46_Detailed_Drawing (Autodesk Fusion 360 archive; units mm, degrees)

design "46 Detailed Drawing"
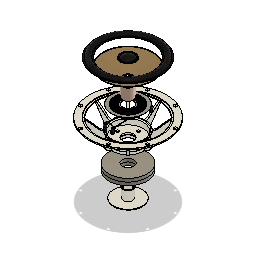
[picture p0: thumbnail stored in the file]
part number: 6 Inch Woofer
parameter "VoiceCoilDia" = 30
parameter "VoiceCoilThickness" = 2
parameter "PoleDia" = 22 (= "VoiceCoilDia + -4 * VoiceCoilThickness")
parameter "BasketThickness" = 3
parameter "SpiderMountingSurface" = 46 (= "SpacerDiameter / 2 + 2 * BasketThickness")
parameter "adsk_nomlen" = 10
parameter "adsk_headh" = 2.7
parameter "adsk_headdia" = 9.3
parameter "adsk_nomdia" = 5
parameter "adsk_headang" = 90
parameter "adsk_phildia" = 5.2
parameter "adsk_philwidth" = 0.66
parameter "adsk_phildepth" = 3.2
parameter "adsk_shnkdia" = 4.5092
parameter "adsk_thrlen" = 5.7
parameter "adsk_pitch1" = 0.8
parameter "adsk_startlen" = 0.4908
parameter "adsk_midfillet" = 0.5 (= "adsk_nomdia * 0.1")
parameter "adsk_endpointdia" = 4.0185
parameter "MountingHoleDia" = 86.2 (= "( ( SpeakerSize * 25.4 / 2 ) * 1 mm ) + ( FlangeSize / 2 )")
parameter "ConeAngle" = 70
parameter "CoverThickness" = 2.5
sketch "Sketch1" plane through (0, 0, 0) normal (0, 1, 0) x axis (1, 0, 0)
  circle C1 centre (0, 0) radius 50
  circle C2 centre (0, 0) radius 18
  point P1 (0, 0)
  point P2 (0, 0)
  point P3 (0, 0)
  coincident P1 P2
  coincident P1 P3
  dimension "MagnetDia" diameter C1 = 100
  dimension "MagnetThruHole" diameter C2 = 36 (= "VoiceCoilDia + 3 * VoiceCoilThickness")
extrude "Extrude1" new body sketch "Sketch1" along normal blind 10 named "MagnetThickness"
as_built_joint "As-built1"
chamfer "Chamfer2" distance 0.5
rectangular_pattern "R-Pattern1" uSpaceDistance 10 (= "MagnetThickness") vSpaceDistance 0
sketch "Sketch1" plane through (0, 0, 0) normal (0, -1, 0) x axis (1, 0, 0)
  circle C1 centre (0, 0) radius 18
  circle C2 centre (0, 0) radius 37.5
  circle C3 centre (0, 0) radius 18
  circle C4 centre (0, 0) radius 6
  circle C5 centre (0, 0) radius 49.5
  concentric C1 C2
  concentric C2 C3
  concentric C2 C4
  dimension "BottomPlateDiameter" diameter C2 = 75 (= "MagnetDia * 0.75")
  dimension "d12" diameter C3 = 36 (= "MagnetThruHole")
  dimension "VentHole" diameter C4 = 12 (= "VoiceCoilDia / 2.5")
extrude "Extrude1" new body sketch "Sketch1" profile of C1 C2 C3 C4 along normal blind 9 (= "VentHole * 0.75") named "BottomPlateThickness"
fillet "Fillet1" radius 37.5 (= "BottomPlateDiameter / 2")
extrude "Extrude2" add of existing geometry blind 2 named "BottomPlateOffset"
fillet "Fillet2" radius 3 (= "VentHole / 4")
sketch "Sketch4" plane through (0, 2, 0) normal (0, 1, 0) x axis (-1, 0, 0)
  circle C1 centre (0, 0) radius 37.5
  circle C2 centre (0, 0) radius 15
  circle C3 centre (0, 0) radius 11
  circle C4 centre (0, 0) radius 9
  point P1 (0, 0)
  point P3 (0, 0)
  point P4 (0, 0)
  coincident P1 P3
  coincident P1 P4
  dimension "d23" diameter C2 = 30 (= "VoiceCoilDia")
  dimension "d24" diameter C3 = 22 (= "PoleDia")
extrude "Extrude3" add sketch "Sketch4" profile of C2 C3 along normal blind 30 (= "( MagnetCount + 1 ) * MagnetThickness") named "PoleLength"
chamfer "Chamfer1" distance 1
joint "Assemble" alignAngle 0 alignOffsetX 0 alignOffsetY 0 alignOffsetZ 0
sketch "Sketch1" plane through (0, 0, 0) normal (0, 1, 0) x axis (1, 0, 0)
  line L1 (0, 18) -> (0, 0)
  line L2 (0, 40) -> (0, 18)
  circle C1 centre (0, 0) radius 18
  circle C2 centre (0, 0) radius 40
  circle C3 centre (0, 0) radius 29
  point P1 (0, 0)
  point P2 (0, 0)
  point P3 (0, 0)
  point P4 (0, 0)
  point P5 (0, 18)
  point P6 (0, 40)
  point P8 (0, 29)
  coincident P1 P2
  coincident P1 P3
  coincident P2 P4
  coincident C1 P5
  vertical L1
  coincident C2 P6
  parallel L1 L2
  concentric C2 C3
  midpoint L2 P8
  coincident C3 P8
  dimension "d32" diameter C1 = 36 (= "MagnetThruHole")
  dimension "SpacerDiameter" diameter C2 = 80 (= "MagnetDia * 0.8")
extrude "Extrude1" new body sketch "Sketch1" profile of C1 C2 along normal blind 10 (= "MagnetThickness")
hole "Hole1" HoleDepth 10 (= "MagnetThickness") HoleDiameter 4.234 TipAngle 118
circular_pattern "C-Pattern1" countU 3 (= "SpeakerSize / 2") TotalAngle 360
chamfer "Chamfer1" distance 1
joint "Assemble" alignAngle 0 alignOffsetX 0 alignOffsetY 0 alignOffsetZ 0
sketch "Sketch1" plane through (0, 0, 0) normal (0, 1, 0) x axis (1, 0, 0)
  circle C1 centre (0, 0) radius 43
  circle C2 centre (0, 0) radius 18
  circle C3 centre (0, 29) radius 2.117
  point P1 (0, 0)
  point P2 (0, 0)
  point P3 (0, 0)
  coincident P1 P2
  coincident P1 P3
  dimension "d47" diameter C1 = 86 (= "SpacerDiameter + 2 * BasketThickness")
  dimension "d48" diameter C2 = 36 (= "MagnetThruHole")
extrude "Extrude1" new body sketch "Sketch1" against normal blind 5 (magnitude of "MagnetThickness / -2")
hole "Hole1" HoleDepth 10 HoleDiameter 5.5 TipAngle 118 CSDiameter 10.4 CSAngle 90
circular_pattern "C-Pattern1" countU 3 (= "SpeakerSize / 2") TotalAngle 360
joint "Assemble" alignAngle 0 alignOffsetX 0 alignOffsetY 0 alignOffsetZ 0
work_plane "WorkPlane1" RotateAngle 30 (= "90.0 deg - ( ( 360 / SpeakerSize ) * 1 deg )")
sketch "Sketch3" plane through (0, -22.875, 0) normal (0.5, 0, 0.866) x axis (0, 1, 0)
  line L1 (17.875, -43) -> (17.875, 43)
  line L2 (22.875, 43) -> (22.875, -43)
  line L3 (17.875, 18) -> (17.875, -18)
  line L4 (22.875, -18) -> (22.875, 18)
  line L5 (22.875, 18) -> (22.875, -18)
  line L6 (100, 0) -> (22.875, 0)
  line L7 (42.875, -46) -> (42.875, -43)
  line L8 (22.875, -46) -> (42.875, -46)
  line L9 (22.875, -43) -> (22.875, -46)
  line L10 (42.875, -43) -> (42.875, -46)
  line L11 (39.875, -46) -> (42.875, -46)
  line L12 (39.875, -43) -> (39.875, -46)
  line L13 (22.875, -43) -> (39.875, -43)
  line L14 (22.875, -40) -> (22.875, -43)
  line L15 (39.875, -40) -> (22.875, -40)
  line L16 (17.875, -53.0255) -> (17.875, -43)
  line L17 (60.975, -77.8667) -> (17.875, -53.0255)
  line L18 (60.975, -71.2) -> (46.9451, -56.2731)
  line L19 (60.975, -93.7) -> (60.975, -78.7)
  line L20 (65.475, -96.2) -> (60.975, -96.2)
  line L21 (65.475, -76.2) -> (65.475, -96.2)
  line L22 (60.975, -76.2) -> (65.475, -76.2)
  line L23 (60.975, -96.2) -> (60.975, -76.2)
  line L24 (22.875, -43) -> (17.875, -43)
  line L25 (17.875, -40) -> (17.875, -43)
  line L26 (22.875, -40) -> (17.875, -40)
  line L27 (63.225, -76.2) -> (60.975, -76.2)
  line L28 (63.225, -71.2) -> (63.225, -76.2)
  line L29 (60.975, -71.2) -> (63.225, -71.2)
  line L30 (60.975, -76.2) -> (60.975, -71.2)
  arc A1 centre (39.875, -43) radius 3 clockwise from (39.875, -40) to (42.875, -43)
  arc A2 centre (57.875, -46) radius 15 clockwise from (46.9451, -56.2731) to (42.875, -46)
  point P9 (22.875, -18)
  point P10 (22.875, -18)
  point P8 (22.875, 18)
  point P11 (22.875, 18)
  point P12 (22.875, 0)
  point P14 (42.875, 0)
  point P4 (22.875, -43)
  point P17 (22.875, -43)
  point P19 (22.875, -43)
  point P20 (22.875, -43)
  point P3 (17.875, -43)
  point P27 (17.875, -43)
  point P28 (60.975, -93.7)
  point P34 (60.975, -93.7)
  point P29 (60.975, -78.7)
  point P35 (60.975, -78.7)
  point P36 (60.975, -86.2)
  point P42 (17.875, -43)
  point P43 (17.875, -40)
  point P47 (60.975, -77.8667)
  point P15 (42.875, -46)
  point P39 (42.875, -46)
  point P22 (39.875, -43)
  point P26 (39.875, -43)
  point P23 (39.875, -43)
  point P37 (17.875, -53.0255)
  point P38 (17.875, -53.0255)
  point P16 (22.875, -46)
  point P18 (39.875, -46)
  point P30 (60.975, -96.2)
  point P31 (65.475, -96.2)
  point P32 (65.475, -76.2)
  point P33 (60.975, -76.2)
  point P44 (63.225, -76.2)
  point P45 (63.225, -71.2)
  point P46 (60.975, -71.2)
  coincident P9 P10
  coincident P8 P11
  midpoint L2 P12
  perpendicular L5 L6
  coincident L6 P14
  perpendicular L6 L7
  perpendicular L2 L8
  coincident P4 P17
  perpendicular L8 L9
  perpendicular L8 L10
  perpendicular L7 L11
  coincident P4 P19
  perpendicular L9 L13
  vertical L12
  coincident P4 P20
  perpendicular L13 L14
  horizontal L15
  coincident P14 L7
  tangent L7 A1
  tangent L15 A1
  coincident P3 P27
  parallel L1 L16
  vertical L19
  perpendicular L20 L21
  perpendicular L21 L22
  coincident P28 P34
  coincident P29 P35
  midpoint L19 P36
  perpendicular L20 L23
  midpoint P36 L23
  tangent L18 A2
  coincident P3 P42
  coincident L1 P43
  parallel L1 L25
  horizontal L26
  horizontal L27
  vertical L28
  horizontal L29
  vertical L30
  coincident L23 P47
  coincident P15 P39
  tangent L7 A2
  coincident P22 P26
  coincident P23 P26
  coincident P37 P38
  dimension "SpiderDepth" distance P15 P16 = 20
  dimension "d70" distance P15 P18 = 3 (= "BasketThickness")
  dimension "d73" radius A1 = 3 (= "BasketThickness")
  dimension "d75" distance P30 P31 = 4.5 (= "BasketThickness * 1.5")
  dimension "d77" distance L6 L22 = 76.2 (= "( SpeakerSize * 25.4 / 2 ) * 1 mm")
  dimension "FlangeSize" distance P31 P32 = 20
  dimension "d79" distance P34 P35 = 15 (= "FlangeSize * 0.75")
  dimension "d80" distance L2 L23 = 38.1 (= "( SpeakerSize * 25.4 / 4 ) * 1 mm")
  dimension "d84" radius A2 = 15
  dimension "d95" distance P33 P44 = 2.25 (= "BasketThickness * 0.75")
  dimension "d96" distance P44 P45 = 5 (= "FlangeSize / 4")
  dimension "d178" distance P46 P47 = 6.6667 (= "FlangeSize / 3")
  dimension "d252" distance L15 L24 = 3 (= "BasketThickness")
  dimension "d254" angle L17 L18 = 16.817
  dimension "d259" distance L6 L11 = 46 (= "SpiderMountingSurface")
revolve "Revolve1" sketch "Sketch3" AlongAngle 360
fillet "Fillet2" radius 3 (= "BasketThickness")
chamfer "Chamfer1" distance 1 distance 0.5
extrude "Extrude2" add sketch "Sketch3" profile of L1 L2 L10 L11 L12 L13 L14 L15 A1 L16 L17 L18 L19 L23 A2 L24 L25 L26 along a picked direction distance 3 (= "BasketThickness")
fillet "Fillet3" radius 12 (= "BasketThickness * 4")
chamfer "Chamfer2" distance 0.5
circular_pattern "C-Pattern2" TotalAngle 360
sketch "Sketch4" plane through (0, 42.6, 0) normal (0, 1, 0) x axis (-1, 0, 0)
  line L1 (0, -125) -> (0, 0)
  line L2 (-44.35, -76.8165) -> (0, 0)
  line L3 (-48.1, -83.3116) -> (-44.35, -76.8165)
  circle C1 centre (0, 0) radius 76.7
  circle C2 centre (0, 0) radius 95.7
  circle C3 centre (0, 0) radius 96.2
  point P1 (0, 0)
  point P3 (0, 0)
  point P5 (0, 0)
  point P8 (-48.1, -83.3116)
  point P6 (-44.35, -76.8165)
  coincident P1 P3
  vertical L1
  coincident P1 P5
  coincident C3 P8
  parallel L2 L3
  dimension "d97" angle L1 L2 = 30 (= "( 180 / SpeakerSize ) * 1 deg")
  dimension "d181" distance P6 P8 = 7.5
hole "Hole2" HoleDepth 20 HoleDiameter 5.5 TipAngle 118 CSDiameter 10.4 CSAngle 90
circular_pattern "C-Pattern3" countU 12 TotalAngle 360
sketch "Sketch1" plane through (0, 0, 0) normal (0, 0, 1) x axis (1, 0, 0)
  line L1 (0, 140.5455) -> (0, 0)
  line L2 (71.2, 76.35) -> (75.95, 76.35)
  line L3 (71.2, 75.35) -> (71.2, 76.35)
  line L4 (76.2, 75.35) -> (71.2, 75.35)
  line L5 (76.2, 76.1) -> (76.2, 75.35)
  line L6 (56.2, 76.35) -> (51.45, 76.35)
  line L7 (56.2, 75.35) -> (56.2, 76.35)
  line L8 (51.2, 75.35) -> (56.2, 75.35)
  line L9 (51.2, 76.1) -> (51.2, 75.35)
  line L10 (71.2, 75.35) -> (56.2, 75.35)
  line L11 (0, 50.963) -> (51.2, 75.35)
  line L12 (15, 58.1076) -> (51.2, 75.35)
  line L13 (15.285, 57.1357) -> (53.5255, 75.35)
  line L14 (15, 55.25) -> (15, 56.6843)
  line L15 (14.57, 57.9028) -> (15, 58.1076)
  line L16 (14, 55.25) -> (14, 57)
  line L17 (14.75, 55) -> (14.25, 55)
  line L18 (30.3147, 35) -> (19.9147, 35)
  line L19 (-19.9147, 35) -> (-30.3147, 35)
  line L20 (5.2, 35) -> (-5.2, 35)
  line L21 (-39, 20) -> (39, 20)
  line L22 (-40, 35) -> (40, 35)
  line L23 (18, 35) -> (-18, 35)
  circle C1 centre (63.7, 75.35) radius 7.5664
  circle C2 centre (63.7, 75.35) radius 8.5664
  arc A1 centre (75.95, 76.1) radius 0.25 clockwise from (75.95, 76.35) to (76.2, 76.1)
  arc A2 centre (51.45, 76.1) radius 0.25 clockwise from (51.2, 76.1) to (51.45, 76.35)
  arc A3 centre (15.5, 56.6843) radius 0.5 clockwise from (15, 56.6843) to (15.285, 57.1357)
  arc A4 centre (15, 57) radius 1 clockwise from (14, 57) to (14.57, 57.9028)
  arc A5 centre (14.75, 55.25) radius 0.25 clockwise from (15, 55.25) to (14.75, 55)
  arc A6 centre (14.25, 55.25) radius 0.25 clockwise from (14.25, 55) to (14, 55.25)
  point P1 (0, 0)
  point P2 (0, 0)
  point P6 (71.2, 75.35)
  point P10 (56.2, 75.35)
  point P12 (63.7, 75.35)
  point P9 (56.2, 76.35)
  point P14 (56.1336, 75.35)
  point P15 (55.1336, 75.35)
  point P16 (0, 50.963)
  point P17 (15, 58.1076)
  point P4 (76.2, 76.35)
  point P8 (51.2, 76.35)
  point P24 (53.5255, 75.35)
  point P25 (15, 57)
  point P26 (15, 55)
  point P7 (76.2, 75.35)
  point P11 (51.2, 75.35)
  coincident P1 P2
  vertical L1
  horizontal L2
  vertical L3
  horizontal L4
  vertical L5
  horizontal L6
  vertical L7
  horizontal L8
  vertical L9
  horizontal P6 P10
  midpoint L10 P12
  coincident P9 C1
  concentric C1 C2
  coincident C1 P14
  coincident L8 P14
  coincident L8 P15
  coincident C2 P15
  coincident L1 P16
  coincident L11 P17
  coincident P4 L2
  coincident P4 L5
  tangent L2 A1
  tangent L5 A1
  coincident P8 L6
  coincident P8 L9
  tangent L6 A2
  tangent L9 A2
  coincident L8 P24
  parallel L12 L13
  vertical P17 P25
  vertical L14
  parallel L14 L16
  horizontal L17
  coincident P25 L13
  coincident P25 L14
  tangent L13 A3
  tangent L14 A3
  tangent L15 A4
  tangent L16 A4
  parallel L12 L15
  coincident P26 L14
  coincident P26 L17
  tangent L14 A5
  tangent L17 A5
  tangent L16 A6
  tangent L17 A6
  equal A5 A6
  dimension "SurroundThickness" distance P4 P7 = 1
  dimension "d107" distance P8 P11 = 1 (= "SurroundThickness")
  dimension "d108" distance P6 P7 = 5 (= "FlangeSize / 4")
  dimension "d109" distance P10 P11 = 5 (= "FlangeSize / 4")
  dimension "SurroundSize" distance L3 L7 = 15 (= "FlangeSize * 0.75")
  dimension "d111" distance P14 P15 = 1 (= "SurroundThickness")
  dimension "d112" distance L1 L5 = 76.2 (= "( SpeakerSize * 25.4 / 2 ) * 1 mm")
  dimension "d117" radius A1 = 0.25
  dimension "d118" radius A2 = 0.25
  dimension "d119" distance L12 L13 = 1 (= "SurroundThickness")
  dimension "d120" distance P25 P26 = 2 (= "SurroundThickness * 2")
  dimension "d121" distance L14 L16 = 1 (= "SurroundThickness")
  dimension "d122" radius A3 = 0.5 (= "SurroundThickness / 2")
  dimension "d123" radius A4 = 1 (= "SurroundThickness")
  dimension "d124" radius A5 = 0.25 (= "SurroundThickness / 4")
  dimension "d141" distance L1 L14 = 15 (= "VoiceCoilDia / 2")
  dimension "d144" distance L17 L21 = 35 (= "VoiceCoilLength")
  dimension "d282" distance P1 L4 = 75.35 (= "Linear Dimension-14")
revolve "Revolve1" sketch "Sketch1" AlongAngle 360
sketch "Sketch1" plane through (0, 0, 0) normal (0, 0, 1) x axis (1, 0, 0)
  line L1 (0, 104.734) -> (0, 0)
  line L2 (36.8, 55) -> (44.5, 55)
  line L3 (36.8, 56) -> (36.8, 55)
  line L4 (44.5, 56) -> (36.8, 56)
  line L5 (44.5, 55) -> (44.5, 56)
  line L6 (15, 55) -> (17, 55)
  line L7 (15, 20) -> (15, 55)
  line L8 (17, 20) -> (15, 20)
  line L9 (17, 55) -> (17, 20)
  line L10 (-39, 20) -> (39, 20)
  line L11 (17, 55) -> (15, 55)
  line L12 (17, 56.5) -> (17, 55)
  line L13 (15, 56.5) -> (17, 56.5)
  line L14 (15, 55) -> (15, 56.5)
  line L15 (17, 55.5) -> (36.8, 55.5)
  line L16 (17, 56) -> (36.8, 56)
  line L17 (17, 55) -> (17, 56)
  line L18 (36.8, 55) -> (17, 55)
  line L19 (36.8, 56) -> (36.8, 55)
  line L20 (17, 55) -> (36.8, 56)
  line L21 (36.8, 55) -> (17, 56)
  line L22 (43, 55) -> (-43, 55)
  circle C1 centre (26.9, 55.5) radius 1
  circle C2 centre (24.6, 55.5) radius 1
  circle C3 centre (22.3, 55.5) radius 1
  circle C4 centre (20, 55.5) radius 1
  circle C5 centre (29.2, 55.5) radius 1
  circle C6 centre (31.5, 55.5) radius 1
  circle C7 centre (33.8, 55.5) radius 1
  circle C8 centre (36.1, 55.5) radius 1
  point P1 (0, 0)
  point P2 (0, 0)
  point P11 (17, 20)
  point P16 (36.8, 55.5)
  point P17 (17, 55.5)
  point P21 (26.9, 55.5)
  point P22 (26.9, 55.5)
  point P4 (44.5, 55)
  point P7 (44.5, 56)
  point P8 (17, 55)
  point P9 (15, 55)
  point P14 (17, 56.5)
  coincident P1 P2
  vertical L1
  horizontal L2
  vertical L3
  horizontal L4
  vertical L5
  horizontal L6
  vertical L7
  horizontal L8
  vertical L9
  coincident P11 L10
  horizontal L11
  vertical L12
  horizontal L13
  vertical L14
  midpoint L3 P16
  coincident L12 P17
  perpendicular L12 L15
  horizontal L16
  perpendicular L16 L17
  parallel L16 L18
  parallel L17 L19
  coincident L20 P21
  coincident L21 P21
  midpoint L15 P21
  coincident P21 P22
  dimension "SpiderThickness" distance P4 P7 = 1
  dimension "d134" distance P1 L2 = 55
  dimension "d135" distance L1 L3 = 36.8 (= "SpiderMountingSurface * 0.8")
  dimension "d137" distance L1 L7 = 15 (= "VoiceCoilDia / 2")
  dimension "d138" distance P8 P9 = 2 (= "VoiceCoilThickness")
  dimension "VoiceCoilLength" distance P8 P11 = 35 (= "SpiderDepth + MagnetThickness * 1.5")
  dimension "d145" distance P8 P14 = 1.5 (= "SurroundThickness * 1.5")
  dimension "d146" diameter C1 = 2 (= "SpiderThickness * 2")
  dimension "SpiderRad" distance L1 L5 = 44.5 (= "SpiderMountingSurface - BasketThickness / 2")
  dimension "d149" R-Pattern1-uDistance = 2.3 (= "( SpiderMountingSurface / 20 )")
  dimension "d150" R-Pattern1-vDistance = 0
  dimension "d154" R-Pattern2-uDistance = -2.3 (= "-( SpiderMountingSurface / 20 )")
  dimension "d155" R-Pattern2-vDistance = 0
revolve "Revolve1" sketch "Sketch1" AlongAngle 360
revolve "Revolve2" sketch "Sketch1" AlongAngle 360 bodies "Voice Coil"
fillet "Fillet1" radius 0.25 (= "SpiderThickness / 4")
work_plane "WorkPlane3" AlongDistance -52 (= "-( ( SpiderMountingSurface - BasketThickness / 2 ) + ( 7.5 mm ) )")
sketch "Sketch3" plane through (0, 56, 0) normal (0, 1, 0) x axis (-1, 0, 0)
  line L1 (12, -52) -> (12, -10.9545)
  line L2 (11, -10.9545) -> (13, -10.9545)
  line L3 (11, -48.127) -> (11, -10.9545)
  line L4 (13, -10.9545) -> (13, -48.127)
  line L5 (10.9766, -94.0045) -> (13, -10.9545)
  line L6 (12.997, -92.9231) -> (11, -10.9545)
  line L7 (-13, -10.9545) -> (-13, -48.127)
  line L8 (-11, -10.9545) -> (-13, -10.9545)
  line L9 (-11, -48.127) -> (-11, -10.9545)
  line L10 (19, 0) -> (0, 0)
  line L11 (-19, 0) -> (0, 0)
  line L12 (0, -12) -> (0, 0)
  line L13 (-21.75, -52) -> (-0.75, -52)
  circle C1 centre (0, 0) radius 19.134
  circle C2 centre (12, -52) radius 4
  circle C3 centre (-12, -52) radius 4
  circle C4 centre (0, 0) radius 17
  circle C5 centre (0, 0) radius 19
  point P4 (12, -52)
  point P5 (12, -52)
  point P10 (12, -52)
  point P11 (13, -48.127)
  point P12 (11, -48.127)
  point P14 (-13, -10.9545)
  point P18 (0, 0)
  point P20 (0, 0)
  point P21 (19, 0)
  point P22 (0, 0)
  point P23 (-19, 0)
  point P19 (0, 0)
  point P24 (0, 0)
  point P6 (13, -10.9545)
  point P3 (12, -10.9545)
  point P7 (11, -10.9545)
  point P15 (-11, -10.9545)
  point P13 (-13, -48.127)
  point P16 (-11, -48.127)
  point P26 (-0.75, -52)
  vertical L1
  coincident P4 P5
  horizontal L2
  perpendicular L2 L3
  parallel L3 L4
  coincident L5 P10
  coincident L6 P10
  coincident P5 P10
  coincident C2 P11
  coincident C2 P12
  coincident P14 C4
  coincident P18 P20
  coincident C5 P21
  coincident P18 P22
  coincident C5 P23
  coincident P19 P24
  perpendicular L10 L12
  coincident P6 C4
  midpoint P3 L2
  symmetric C2 C3 L12
  symmetric L4 L7 L12
  symmetric L3 L9 L12
  symmetric P7 P15 L12
  coincident P13 C3
  coincident P16 C3
  horizontal P5 P26
  dimension "d159" diameter C2 = 8
  dimension "TinselLeadWidth" distance P6 P7 = 2
  dimension "d232" distance C4 C5 = 2 (= "TinselLeadWidth")
  dimension "d263" distance L1 L12 = 12
component_from_bodies "Body->Comp2"
extrude "Extrude1" sketch "Sketch3" profile of C1 C2 L3 L4 L7 L9 C3 C4 C5 L10 L11 blind 0.5 named "TinselLeadThickness" from offset -0.5 bodies "TinselLeads"
extrude "Extrude2" sketch "Sketch3" profile of C2 C3 L13 blind 1.5 (= "TinselLeadThickness * 3") second side blind 15 (= "TinselLeadThickness * 30") from offset -0.5 bodies "Terminals"
work_plane "WorkPlane1" RotateAngle 270
sketch "Sketch4" plane through (-12, 53.5787, -56) normal (0, 0, -1) x axis (-1, 0, 0)
  line L1 (-24, -12.5787) -> (-24, -7.5787)
  line L2 (0, -12.5787) -> (0, -7.5787)
  line L3 (4, -12.5787) -> (-4, -12.5787)
  line L4 (-20, -12.5787) -> (-28, -12.5787)
  circle C1 centre (-24, -7.5787) radius 2.5
  circle C2 centre (0, -7.5787) radius 2.5
  point P2 (-24, -7.5787)
  point P4 (-24, -7.5787)
  point P3 (0, -7.5787)
  point P6 (0, -7.5787)
  point P5 (-24, -12.5787)
  point P7 (0, -12.5787)
  coincident P2 P4
  coincident P3 P6
  vertical L2
  midpoint P5 L4
  perpendicular L1 L4
  midpoint P7 L3
  dimension "WireGauge" diameter C1 = 5
  dimension "d182" diameter C2 = 5
  dimension "d183" distance P4 P5 = 5 (= "WireGauge")
  dimension "d184" distance P6 P7 = 5 (= "WireGauge")
extrude "Extrude3" cut sketch "Sketch4" profile of C1 C2 against normal blind 8
sketch "Sketch1" plane through (0, 0, 0) normal (0, 0, 1) x axis (1, 0, 0)
  line L1 (0, 50.963) -> (51.2, 75.35)
  line L2 (0, 55.963) -> (0, 50.963)
  line L3 (22.3021, 61.5857) -> (27.7191, 64.1658)
  line L4 (26.859, 65.9715) -> (27.7191, 64.1658)
  line L5 (23.5372, 64.3893) -> (26.859, 65.9715)
  line L6 (0, 80.963) -> (0, 50.963)
  line L7 (14.57, 57.9028) -> (22.3021, 61.5857)
  circle C1 centre (0, 55.963) radius 23
  circle C2 centre (0, 55.963) radius 25
  point P3 (0, 50.963)
  point P4 (0, 50.963)
  point P6 (27.7191, 64.1658)
  point P7 (22.3021, 61.5857)
  point P5 (0, 55.963)
  point P9 (0, 55.963)
  point P11 (23.5372, 64.3893)
  point P12 (0, 50.963)
  point P13 (0, 80.963)
  point P14 (14.57, 57.9028)
  point P15 (14.57, 57.9028)
  point P8 (26.859, 65.9715)
  point P10 (0, 55.963)
  coincident P3 P4
  vertical L2
  coincident L1 P6
  coincident L1 P7
  parallel L1 L3
  perpendicular L1 L4
  coincident P5 P9
  coincident P7 C1
  concentric C1 C2
  coincident C2 P11
  perpendicular L4 L5
  coincident P3 P12
  coincident C2 P13
  vertical L6
  coincident P14 P15
  dimension "DustCapThickness" distance C1 C2 = 2
  dimension "d193" distance P6 P8 = 2 (= "DustCapThickness")
  dimension "d194" distance P6 P7 = 6 (= "DustCapThickness * 3")
  dimension "DustCapCurve" diameter C2 = 50
  dimension "DustCapOffset" distance P10 P12 = 5
sketch "Sketch5" plane through (0, 56, 0) normal (0, 1, 0) x axis (-1, 0, 0)
  line L1 (-12, -229.6377) -> (-12, -54.8723)
  line L2 (12, -611.627) -> (12, -54.8723)
  line L3 (-10, -54.8723) -> (-10, -44.8999)
  line L4 (-14, -54.8723) -> (-10, -54.8723)
  line L5 (-14, -43.8178) -> (-14, -54.8723)
  line L6 (-10, -54.8723) -> (-8311.3248, -725447.2893)
  line L7 (-14, -54.8723) -> (3910.1152, -342954.7674)
  line L8 (10, -54.8723) -> (10, -44.8999)
  line L9 (14, -54.8723) -> (10, -54.8723)
  line L10 (14, -43.8178) -> (14, -54.8723)
  line L11 (10, -54.8723) -> (9.739, 17.7761)
  line L12 (14, -54.8723) -> (-1217.7809, -342954.7674)
  line L13 (15.5, -52) -> (12, -52)
  line L14 (8.5, -52) -> (12, -52)
  line L15 (-8.5, -52) -> (-12, -52)
  line L16 (-15.5, -52) -> (-12, -52)
  circle C1 centre (12, -52) radius 4
  circle C2 centre (-12, -52) radius 4
  circle C3 centre (0, 0) radius 34.666
  arc A1 centre (-12, -52) radius 3.5 clockwise from (-15.5, -52) to (-8.5, -52)
  arc A2 centre (12, -52) radius 3.5 clockwise from (8.5, -52) to (15.5, -52)
  circle C4 centre (0, 0) radius 46
  circle C5 centre (0, 0) radius 44.25
  arc A3 centre (0, 0) radius 46 clockwise from (38.2524, -25.5491) to (3, -45.9021)
  circle C6 centre (0, 0) radius 35.234
  circle C7 centre (0, 0) radius 36.966
  arc A4 centre (0, 0) radius 46 clockwise from (-41.2524, -20.353) to (-41.2524, 20.353)
  arc A5 centre (0, 0) radius 46 clockwise from (-41.2524, -20.353) to (-41.2524, 20.353)
  arc A6 centre (0, 0) radius 46 clockwise from (3, 45.9021) to (38.2524, 25.5491)
  arc A7 centre (0, 0) radius 46 clockwise from (3, 45.9021) to (38.2524, 25.5491)
  point P10 (-12, -229.6377)
  point P3 (-12, -229.6377)
  point P15 (12, -611.627)
  point P5 (12, -611.627)
  point P17 (12, -52)
  point P18 (-12, -52)
  point P7 (3910.1152, -342954.7674)
  point P12 (-1217.7809, -342954.7674)
  point P2 (-12, -54.8723)
  point P4 (12, -54.8723)
  point P26 (12, -52)
  point P28 (12, -52)
  point P30 (-12, -52)
  point P32 (-12, -52)
  point P8 (-10, -54.8723)
  point P14 (14, -54.8723)
  point P22 (14, -43.8178)
  point P23 (10, -44.8999)
  point P21 (-10, -44.8999)
  point P20 (-14, -43.8178)
  point P9 (-14, -54.8723)
  point P13 (10, -54.8723)
  point P31 (-8.5, -52)
  point P29 (8.5, -52)
  vertical L1
  parallel L1 L2
  parallel L3 L5
  coincident L6 P10
  coincident L7 P10
  coincident P3 P10
  parallel L8 L10
  coincident L11 P15
  coincident L12 P15
  coincident P5 P15
  coincident L2 P17
  coincident L1 P18
  horizontal P7 P12
  vertical L8
  vertical L3
  horizontal L9
  horizontal L4
  midpoint P2 L4
  midpoint P4 L9
  coincident P17 P26
  horizontal L13
  coincident P17 P28
  parallel L13 L14
  coincident P18 P30
  parallel L13 L15
  coincident P18 P32
  parallel L15 L16
  concentric C2 A1
  concentric C1 A2
  coincident P8 A1
  coincident P14 A2
  concentric C3 C4
  coincident P22 C4
  coincident P23 C4
  coincident P21 C4
  coincident P20 C4
  dimension "d185" distance P8 P9 = 4 (= "TinselLeadWidth * 2")
  dimension "d186" distance P13 P14 = 4 (= "TinselLeadWidth * 2")
  dimension "d291" distance P18 P31 = 3.5
  dimension "d292" distance P28 P29 = 3.5
  dimension "d293" diameter C4 = 92 (= "2 * ( SpiderMountingSurface - BasketThickness / 2 ) + BasketThickness")
extrude "Extrude4" sketch "Sketch5" profile of L3 L5 L8 L10 C1 C2 C4 blind 1 from offset -3 (= "-SpiderThickness - ( BasketThickness / 2 ) - 0.5 mm")
component_from_bodies "Body->Comp1"
joint "Assemble10" alignAngle 0 alignOffsetX 0 alignOffsetY 0 alignOffsetZ 0
joint "Assemble5" alignAngle 0 alignOffsetX 0 alignOffsetY 0 alignOffsetZ 0
revolve "Revolve1" sketch "Sketch1" AlongAngle 360
fillet "Fillet1" radius 1 (= "DustCapThickness / 2")
revolve "Revolve1" sketch "Sketch1" AlongAngle 360
component_from_bodies "Body->Comp1"
joint "Assemble" alignAngle 0 alignOffsetX 0 alignOffsetY 0 alignOffsetZ 0
joint "Assemble" alignAngle 0 alignOffsetX 0 alignOffsetY 0 alignOffsetZ 0
joint "Assemble" alignAngle 0 alignOffsetX 0 alignOffsetY 0 alignOffsetZ 0
as_built_joint "As-built2"
chamfer "Chamfer2" distance 0.5
work_plane "WorkPlane2" AlongDistance -4
sketch "Sketch7" plane through (-12, 53.5787, -52) normal (0, 0, -1) x axis (-1, 0, 0)
  line L1 (-20.5, 3.9213) -> (-27.5, 3.9213)
  line L2 (3.5, 3.9213) -> (-3.5, 3.9213)
  line L3 (-24, 5.4213) -> (-24, 3.9213)
  line L4 (-3.5, 8.9213) -> (-20.5, 8.9213)
  line L5 (0, 3.9213) -> (0, 5.4213)
  arc A1 centre (-20.5, 5.4213) radius 3.5 clockwise from (-24, 5.4213) to (-20.5, 8.9213)
  arc A2 centre (-3.5, 5.4213) radius 3.5 clockwise from (-3.5, 8.9213) to (0, 5.4213)
  point P6 (-24, 3.9213)
  point P8 (0, 3.9213)
  point P7 (-24, 8.9213)
  midpoint L1 P6
  perpendicular L1 L3
  perpendicular L3 L4
  midpoint L2 P8
  vertical L5
  coincident P7 L3
  coincident P7 L4
  tangent L3 A1
  tangent L4 A1
  tangent L4 A2
  tangent L5 A2
  equal A1 A2
  dimension "d297" distance P6 P7 = 5
  dimension "d298" radius A1 = 3.5
pipe "Pipe2" SectionSize 2 SectionThickness 0.5
mirror "Mirror1" mirrorStitchTolerance 0.1 bodies "TinselLeads (1)", "Terminals (1)"
as_built_joint "As-built7"
canvas "Canvas4"
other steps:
base_feature "Base Feature1" bodies "Voice Coil"
base_feature "Base Feature1"
base_feature "Base Feature1"
thread "Thread1" ThreadOffset 0 ThreadDepth 10
create_component "CreateComponent1" alignAngle 0 alignOffsetX 0 alignOffsetY 0 alignOffsetZ 3.975 alignAngle 0 alignOffsetX 0 alignOffsetY 0 alignOffsetZ 3.975 alignAngle 0 alignOffsetX 0 alignOffsetY 0 alignOffsetZ 3.975 alignAngle 0 alignOffsetX 0 alignOffsetY 0 alignOffsetZ 3.975 alignAngle 0 alignOffsetX 0 alignOffsetY 0 alignOffsetZ 3.975 alignAngle 0 alignOffsetX 0 alignOffsetY 0 alignOffsetZ 3.975 alignAngle 0 alignOffsetX 0 alignOffsetY 0 alignOffsetZ 3.975 alignAngle 0 alignOffsetX 0 alignOffsetY 0 alignOffsetZ 3.975 alignAngle 0 alignOffsetX 0 alignOffsetY 0 alignOffsetZ 3.975
create_component "CreateComponent2"
joint_origin "JointOrigin1"
joint_origin "JointOrigin1"
create_component "CreateComponent3"
joint_origin "JointOrigin1"
joint_origin "JointOrigin2"
create_component "CreateComponent4"
joint_origin "JointOrigin1"
joint_origin "JointOrigin2"
create_component "CreateComponent5"
create_component "CreateComponent6"
create_component "CreateComponent7"
create_component "CreateComponent1"
create_component "CreateComponent2"
remove_body "RemoveBody1"
joint_origin "JointOrigin1"
joint_origin "JointOrigin1"
create_component "CreateComponent1"
remove_body "RemoveBody1"
create_component "CreateComponent2"
remove_body "RemoveBody2"
joint_origin "JointOrigin2"
joint_origin "JointOrigin4"
joint_origin "JointOrigin1"
joint_origin "JointOrigin2"
joint_origin "JointOrigin2"
joint_origin "JointOrigin5"
joint_origin "JointOrigin3"
joint_origin "JointOrigin6"
named bodies: "TinselLeads", "Body4 (1)", "Voice Coil", "Terminals", "TinselLeads (1)", "Terminals (1)"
